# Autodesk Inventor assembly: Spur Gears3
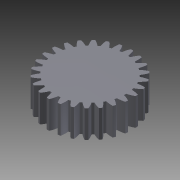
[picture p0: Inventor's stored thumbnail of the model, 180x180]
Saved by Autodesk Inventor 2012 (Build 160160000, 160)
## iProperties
Created: 2017-01
Part Number: Spur Gears3
Document SubType Name: Assembly
Designer: omaro
Categories: <?xml version="1.0" encoding="UTF-16"?> <MemberInstance><Categories><FamilyTemplate/><ParamToTemplateMap><ParamToTemplate><ParamToTemplate CategoryParameter="//
ClientObjectVersion: 1
Author: omaro
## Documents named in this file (2)
- C:\Users\Elkawokgy\Downloads\New folder\Spur Gears3.iam
- C:\Projects\GateProject-master\GateProjectMain\Hardware\Mechanical\Assembly1\Design Accelerator\Spur Gear21.ipt
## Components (1 placed, 1 different names)
1. Spur Gear2:1
